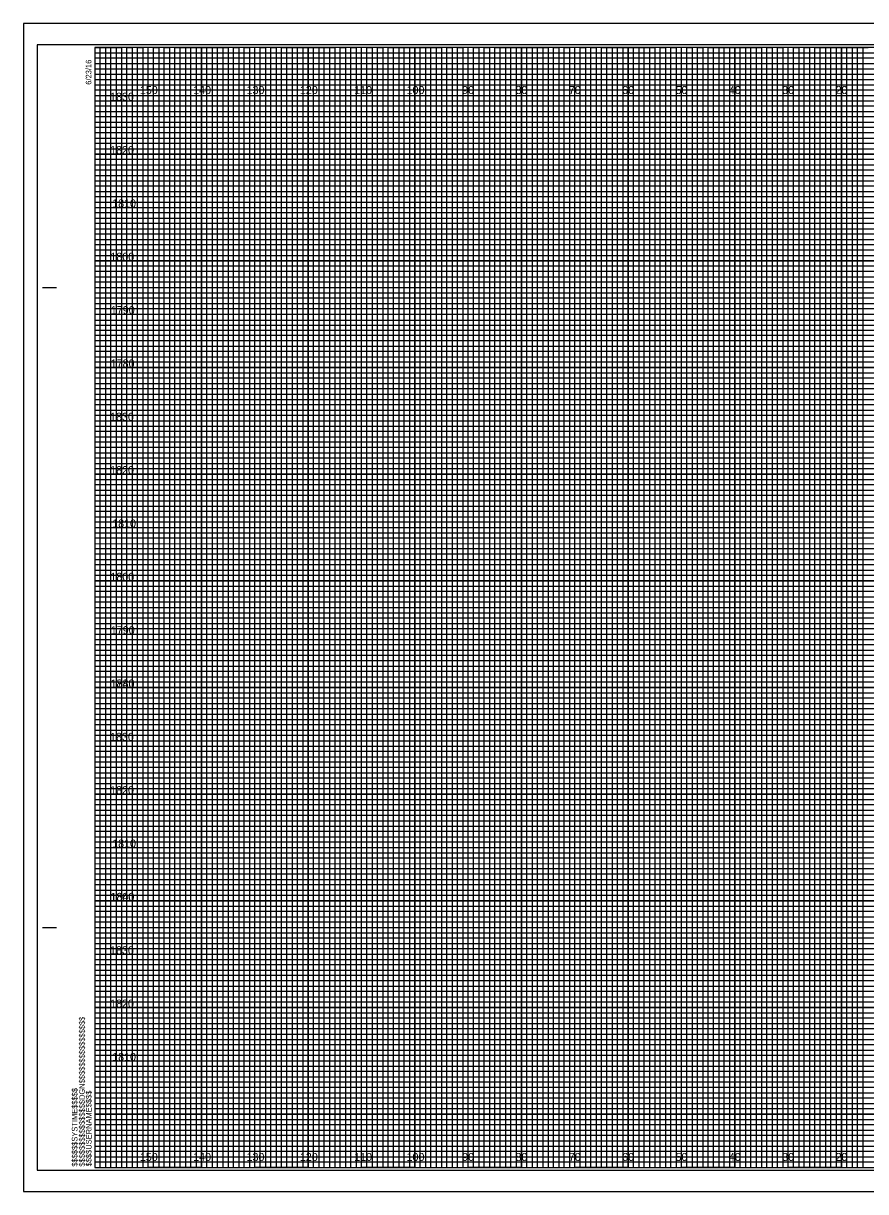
# Model space of a CAD drawing. Extents: x -13 to 323, y -5 to 874.
# Drawn here: x -13.4 to 144.5, y -4.5 to 214.5 of the extents above; entities that cross this region are included whole.
import ezdxf

# ---------------------------------------------------------------- set-up
doc = ezdxf.new("R2010")
doc.units = 0
for name, color, linetype in [('Prop XS Earthwork Shape', 7, 'Continuous'), ('Raster_Level_0', 7, 'Continuous'), ('Scratch_Level_1', 7, 'Continuous'), ('Scratch_Level_3', 7, 'Continuous'), ('Sheet Cross Section CELL', 7, 'Continuous'), ('Sheet Cross Section Grid Minor 1 CELL', 7, 'Continuous'), ('Sheet Cross Section Grid Minor 2 CELL', 7, 'Continuous'), ('Sheet Cutting Line CELL', 7, 'Continuous'), ('Sheet DOT Grid CELL', 7, 'Continuous'), ('Sheet Plot Border Inside CELL', 7, 'Continuous'), ('Sheet Plot Border Outside CELL', 7, 'Continuous')]:
    doc.layers.add(name, color=color, linetype=linetype)

msp = doc.modelspace()

# ---------------------------------------------------------------- linework, layer by layer
at = {"layer": 'Prop XS Earthwork Shape'}
for points in [[(0, 210), (5, 210), (5, 0), (15, 0), (15, 210), (25, 210), (25, 0), (35, 0), (35, 210), (45, 210), (45, 0), (55, 0), (55, 210), (65, 210), (65, 0), (75, 0), (75, 210), (85, 210), (85, 0), (95, 0), (95, 210), (105, 210), (105, 0), (115, 0), (115, 210), (125, 210), (125, 0), (135, 0), (135, 210), (145, 210)], [(0, 205), (275, 205)], [(0, 185), (320, 185), (320, 195), (0, 195)], [(0, 165), (320, 165), (320, 175), (0, 175)], [(0, 145), (320, 145), (320, 155), (0, 155)], [(0, 125), (320, 125), (320, 135), (0, 135)], [(0, 105), (320, 105), (320, 115), (0, 115)], [(0, 85), (320, 85), (320, 95), (0, 95)], [(0, 65), (320, 65), (320, 75), (0, 75)], [(0, 45), (320, 45), (320, 55), (0, 55)], [(0, 25), (320, 25), (320, 35), (0, 35)], [(0, 5), (320, 5), (320, 15), (0, 15)]]:
    msp.add_lwpolyline(points, dxfattribs=at)
at = {"layer": 'Scratch_Level_1'}
for p, q in [((10, 210), (0, 210)), ((10, 0), (10, 210)), ((30, 210), (20, 210)), ((20, 210), (20, 0)), ((30, 0), (30, 210)), ((50, 210), (40, 210)), ((40, 210), (40, 0)), ((50, 0), (50, 210)), ((70, 210), (60, 210)), ((60, 210), (60, 0)), ((70, 0), (70, 210)), ((90, 210), (80, 210)), ((80, 210), (80, 0)), ((90, 0), (90, 210)), ((110, 210), (100, 210)), ((100, 210), (100, 0)), ((110, 0), (110, 210)), ((130, 210), (120, 210)), ((120, 210), (120, 0)), ((130, 0), (130, 210)), ((150, 210), (140, 210)), ((140, 210), (140, 0)), ((20, 0), (10, 0)), ((40, 0), (30, 0)), ((60, 0), (50, 0)), ((80, 0), (70, 0)), ((100, 0), (90, 0)), ((120, 0), (110, 0)), ((140, 0), (130, 0))]:
    msp.add_line(p, q, dxfattribs=at)
for points in [[(0, 200), (320, 200), (320, 190), (0, 190)], [(0, 180), (320, 180), (320, 170), (0, 170)], [(0, 160), (320, 160), (320, 150), (0, 150)], [(0, 140), (320, 140), (320, 130), (0, 130)], [(0, 120), (320, 120), (320, 110), (0, 110)], [(0, 100), (320, 100), (320, 90), (0, 90)], [(0, 80), (320, 80), (320, 70), (0, 70)], [(0, 60), (320, 60), (320, 50), (0, 50)], [(0, 40), (320, 40), (320, 30), (0, 30)], [(0, 20), (320, 20), (320, 10), (0, 10)]]:
    msp.add_lwpolyline(points, dxfattribs=at)
at = {"layer": 'Sheet Cross Section CELL'}
for p, q in [((-9.8, 165), (-7.3, 165)), ((-9.7, 165), (-7.2, 165)), ((-9.8, 45), (-7.3, 45)), ((-9.7, 45), (-7.2, 45)), ((0, 0), (0, 0)), ((0, 0), (0, 0)), ((0, 0), (0, 0)), ((0, 0), (0, 0)), ((0, 0), (0, 0)), ((0, 0), (0, 0)), ((0, 0), (0, 0))]:
    msp.add_line(p, q, dxfattribs=at)
msp.add_lwpolyline([(320, 210), (0, 210), (0, 0), (320, 0)], close=True, dxfattribs=at)
at = {"layer": 'Sheet Cross Section Grid Minor 1 CELL'}
for p, q in [((0, 209), (260, 209)), ((260, 207.98), (0, 207.98)), ((0, 207.98), (0, 207)), ((0, 207), (260, 207)), ((260, 205.89), (0, 205.89)), ((0, 205.89), (0, 204)), ((0, 204), (320, 204))]:
    msp.add_line(p, q, dxfattribs=at)
for points in [[(0, 203), (270, 203), (320, 203), (320, 202), (0, 202)], [(0, 201), (320, 201), (320, 199), (0, 199)], [(0, 198), (320, 198), (320, 197), (0, 196.98)], [(0, 196), (320, 196), (320, 194), (0, 194)], [(0, 193), (320, 193), (320, 192), (0, 192)], [(0, 191), (320, 191), (320, 189), (0, 189)], [(0, 188), (320, 188), (320, 187), (0, 187)], [(0, 186), (320, 186), (320, 184), (0, 184)], [(0, 183), (320, 183), (320, 182), (0, 182)], [(0, 181), (320, 181), (320, 179), (0, 179)], [(0, 178), (320, 178), (320, 177), (0, 177)], [(0, 176), (320, 176), (320, 173.95), (320, 173), (320, 172), (0, 172)], [(0, 174), (320, 174), (320, 173), (0, 173)], [(0, 171), (320, 171), (320, 169), (0, 169.03)], [(0, 169.03), (320, 169), (320, 168), (0, 168)], [(0, 167), (320, 167), (320, 166), (0, 166)], [(0, 164), (320, 164), (320, 163), (0, 163)], [(0, 162), (320, 162), (320, 161), (0, 161)], [(-0.07, 158.89), (320, 158.89), (320, 157.88), (-0.07, 157.88)], [(0, 157), (320, 157), (320, 156), (0, 156)], [(0, 154), (320, 154), (320, 153), (0, 153)], [(0, 152), (320, 152), (320, 151), (0, 151)], [(0, 149), (320, 149), (320, 148), (0, 148)], [(0, 147), (320, 147), (320, 146), (0, 146)], [(0, 144), (320, 144), (320, 143), (0, 143)], [(0, 142), (320, 142), (320, 141), (0, 141)], [(0, 139), (320, 139), (319.99, 137.98), (0, 138)], [(0, 137), (320, 137), (320, 136), (0, 136)], [(0, 134), (320, 134), (320, 133), (0, 133)], [(0, 132), (320, 132), (320, 131), (0, 131)], [(0, 129), (320, 129), (320, 128), (0, 128)], [(0, 127), (320, 127), (320, 126), (0, 126)], [(0, 124), (320, 124), (320, 123), (0, 123)], [(0, 122), (320, 122), (320, 121), (0, 121)], [(0, 119), (320, 119), (320, 118), (0, 118)], [(0, 116.99), (320.07, 116.91), (320, 116), (0, 116)], [(0, 114), (320, 114), (320, 113), (0, 113)], [(0, 112), (320, 112), (320, 111), (0, 111)], [(0, 109), (320, 109), (320, 108), (0, 108)], [(0, 107), (320, 107), (320, 106), (0, 106)], [(0, 104), (320, 104), (320, 103), (0, 103)], [(0, 102), (320, 102), (320, 101), (0, 101)], [(0, 99), (320, 99), (320, 98), (0, 98)], [(0, 97), (320, 97), (320, 96), (0, 96)], [(0, 94), (320, 94), (320, 93), (0, 93)], [(0, 92), (320, 92), (320, 91), (0, 91)], [(0, 89), (320, 89), (320, 88), (0, 88)], [(0, 87), (320, 87), (320, 86), (0, 86)], [(0, 84), (320, 84), (320, 83), (0, 83)], [(0, 82), (320, 82), (320, 81), (0, 81)], [(0, 79), (320, 79), (319.99, 77.98), (0, 78)], [(0, 77), (320, 77), (320, 76), (0, 76)], [(0, 74), (320, 74), (320, 73), (0, 73)], [(0, 72), (320, 72), (320, 71), (0, 71)], [(0, 69), (320, 69), (320, 68), (0, 68)], [(0, 67), (320, 67), (320, 66), (0, 66)], [(0, 64), (320, 64), (320, 63), (0, 63)], [(0, 62), (320, 62), (320, 61), (0, 61)], [(0, 59), (320, 59), (320, 58), (0, 58)], [(0, 56.99), (320.07, 56.91), (320, 56), (0, 56)], [(0, 54), (320, 54), (320, 53), (0, 53)], [(0, 52), (320, 52), (320, 51), (0, 51)], [(0, 49), (320, 49), (320, 48), (0, 48)], [(0, 47), (320, 47), (320, 46), (0, 46)], [(0, 44), (320, 44), (320, 43), (0, 43)], [(0, 42), (320, 42), (320, 41), (0, 41)], [(0, 39), (320, 39), (320, 38), (0, 38)], [(0, 37), (320, 37), (320, 36), (0, 36)], [(0, 34), (320, 34), (320, 33), (0, 33)], [(0, 32), (320, 32), (320, 31), (0, 31)], [(0, 29), (320, 29), (320, 28), (0, 28)], [(0, 27), (320, 27), (320, 26), (0, 26)], [(0, 24), (320, 24), (320, 23), (0, 23)], [(0, 22), (320, 22), (320, 21), (0, 21)], [(0, 19), (320, 19), (320, 18), (0, 18)], [(0, 17), (320, 17), (320, 16), (0, 16)], [(0, 14), (320, 14), (320, 13), (0, 13)], [(0, 12), (320, 12), (320, 11), (0, 11)], [(0, 9), (320, 9), (320, 8), (0, 8)], [(0, 7), (320, 7), (320, 6), (0, 6)], [(0, 4), (320, 4), (320, 3), (0, 3)], [(0, 2), (320, 2), (320, 1), (0, 1)]]:
    msp.add_lwpolyline(points, dxfattribs=at)
at = {"layer": 'Sheet Cross Section Grid Minor 2 CELL'}
for points in [[(0, 0), (1, 0), (1, 210), (2, 210), (2, 0)], [(2, 0), (3, 0), (3, 210), (4, 210), (4, 0)], [(5, 0), (6, 0), (6, 210), (7, 210), (7, 0)], [(7, 0), (8, 0), (8, 210), (9, 210), (9, 0)], [(10, 0), (11, 0), (11, 210), (12, 210), (12, 0)], [(12, 0), (13, 0), (13, 210), (14, 210), (14, 0)], [(15, 0), (16, 0), (16, 210), (17, 210), (17, 0)], [(17, 0), (18, 0), (18, 210), (19, 210), (19, 0)], [(20, 0), (21, 0), (21, 210), (22, 210), (22, 0)], [(22, 0), (23, 0), (23, 210), (24, 210), (24, 0)], [(25, 0), (26, 0), (26, 210), (27, 210), (27, 0)], [(27, 0), (28, 0), (28, 210), (29, 210), (29, 0)], [(30, 0), (31, 0), (31, 210), (32, 210), (32, 0)], [(32, 0), (33, 0), (33, 210), (34, 210), (34, 0)], [(35, 0), (36, 0), (36, 210), (37, 210), (37, 0)], [(37, 0), (38, 0), (38, 210), (39, 210), (39, 0)], [(40, 0), (41, 0), (41, 210), (42, 210), (42, 0)], [(42, 0), (43, 0), (43, 210), (44, 210), (44, 0)], [(45, 0), (46, 0), (46, 210), (47, 210), (47, 0)], [(47, 0), (48, 0), (48, 210), (49, 210), (49, 0)], [(50, 0), (51, 0), (51, 210), (52, 210), (52, 0)], [(52, 0), (53, 0), (53, 210), (54, 210), (54, 0)], [(55, 0), (56, 0), (56, 210), (57, 210), (57, 0)], [(57, 0), (58, 0), (58, 210), (59, 210), (59, 0)], [(60, 0), (61, 0), (61, 210), (62, 210), (62, 0)], [(62, 0), (63, 0), (63, 210), (64, 210), (64, 0)], [(65, 0), (66, 0), (66, 210), (67, 210), (67, 0)], [(67, 0), (68, 0), (68, 210), (69, 210), (69, 0)], [(70, 0), (71, 0), (71, 210), (72, 210), (72, 0)], [(72, 0), (73, 0), (73, 210), (74, 210), (74, 0)], [(75, 0), (76, 0), (76, 210), (77, 210), (77, 0)], [(77, 0), (78, 0), (78, 210), (79, 210), (79, 0)], [(80, 0), (81, 0), (81, 210), (82, 210), (82, 0)], [(82, 0), (83, 0), (83, 210), (84, 210), (84, 0)], [(85, 0), (86, 0), (86, 210), (87, 210), (87, 0)], [(87, 0), (88, 0), (88, 210), (89, 210), (89, 0)], [(90, 0), (91, 0), (91, 210), (92, 210), (92, 0)], [(92, 0), (93, 0), (93, 210), (94, 210), (94, 0)], [(95, 0), (96, 0), (96, 210), (97, 210), (97, 0)], [(97, 0), (98, 0), (98, 210), (99, 210), (99, 0)], [(100, 0), (101, 0), (101, 210), (102, 210), (102, 0)], [(102, 0), (103, 0), (103, 210), (104, 210), (104, 0)], [(105, 0), (106, 0), (106, 210), (107, 210), (107, 0)], [(107, 0), (108, 0), (108, 210), (109, 210), (109, 0)], [(110, 0), (111, 0), (111, 210), (112, 210), (112, 0)], [(112, 0), (113, 0), (113, 210), (114, 210), (114, 0)], [(115, 0), (116, 0), (116, 210), (117, 210), (117, 0)], [(117, 0), (118, 0), (118, 210), (119, 210), (119, 0)], [(120, 0), (121, 0), (121, 210), (122, 210), (122, 0)], [(122, 0), (123, 0), (123, 210), (124, 210), (124, 0)], [(125, 0), (126, 0), (126, 210), (127, 210), (127, 0)], [(127, 0), (128, 0), (128, 210), (129, 210), (129, 0)], [(130, 0), (131, 0), (131, 210), (132, 210), (132, 0)], [(132, 0), (133, 0), (133, 210), (134, 210), (134, 0)], [(135, 0), (136, 0), (136, 210), (137, 210), (137, 0)], [(137, 0), (138, 0), (138, 210), (139, 210), (139, 0)], [(140, 0), (141, 0), (141, 210), (142, 210), (142, 0)], [(142, 0), (143, 0), (143, 210), (144, 210), (144, 0)]]:
    msp.add_lwpolyline(points, dxfattribs=at)
at = {"layer": 'Sheet Cutting Line CELL'}
for p, q in [((323.3, 214.5), (-13.4, 214.5)), ((-13.4, 214.5), (-13.4, -4.5)), ((-13.4, -4.5), (323.3, -4.5))]:
    msp.add_line(p, q, dxfattribs=at)
at = {"layer": 'Sheet DOT Grid CELL'}
for p, q in [((10, 0), (10, 210)), ((20, 0), (20, 210)), ((30, 0), (30, 210)), ((40, 0), (40, 210)), ((50, 0), (50, 210)), ((60, 0), (60, 210)), ((70, 0), (70, 210)), ((80, 0), (80, 210)), ((90, 0), (90, 210)), ((100, 0), (100, 210)), ((110, 0), (110, 210)), ((120, 0), (120, 210)), ((130, 0), (130, 210)), ((140, 0), (140, 210)), ((0, 200), (320, 200)), ((0, 190), (320, 190)), ((0, 180), (320, 180)), ((0, 170), (320, 170)), ((0, 160), (320, 160)), ((0, 150), (320, 150)), ((0, 140), (320, 140)), ((0, 130), (320, 130)), ((0, 120), (320, 120)), ((0, 110), (320, 110)), ((0, 100), (320, 100)), ((0, 90), (320, 90)), ((0, 80), (320, 80)), ((0, 70), (320, 70)), ((0, 60), (320, 60)), ((0, 50), (320, 50)), ((0, 40), (320, 40)), ((0, 30), (320, 30)), ((0, 20), (320, 20)), ((0, 10), (320, 10))]:
    msp.add_line(p, q, dxfattribs=at)
at = {"layer": 'Sheet Plot Border Inside CELL'}
msp.add_lwpolyline([(-10.8, -0.5), (322.4, -0.5), (322.4, 210.5), (-10.8, 210.5)], close=True, dxfattribs=at)
at = {"layer": 'Sheet Plot Border Outside CELL'}
msp.add_lwpolyline([(-13.4, -4.5), (323.3, -4.5), (323.3, 214.5), (-13.4, 214.5)], close=True, dxfattribs=at)

# ---------------------------------------------------------------- texts
at = {"layer": 'Raster_Level_0'}
for s, p in [('150', (8.44, 201.25)), ('140', (18.44, 201.25)), ('130', (28.44, 201.25)), ('120', (38.44, 201.25)), ('110', (48.62, 201.25)), ('100', (58.44, 201.25)), ('90', (68.86, 201.25)), ('80', (78.86, 201.25)), ('70', (88.86, 201.25)), ('60', (98.86, 201.25)), ('50', (108.86, 201.25)), ('40', (118.86, 201.25)), ('30', (128.86, 201.25)), ('20', (138.86, 201.25)), ('150', (8.44, 1.25)), ('140', (18.44, 1.25)), ('130', (28.44, 1.25)), ('120', (38.44, 1.25)), ('110', (48.62, 1.25)), ('100', (58.44, 1.25)), ('90', (68.86, 1.25)), ('80', (78.86, 1.25)), ('70', (88.86, 1.25)), ('60', (98.86, 1.25)), ('50', (108.86, 1.25)), ('40', (118.86, 1.25)), ('30', (128.86, 1.25)), ('20', (138.86, 1.25))]:
    msp.add_text(s, height=1.5, dxfattribs=at).set_placement(p)
at = {"layer": 'Scratch_Level_3'}
for s, p in [('1830', (2.86, 200)), ('1820', (2.87, 190)), ('1810', (3.25, 180)), ('1800', (2.92, 170)), ('1790', (3, 160)), ('1780', (2.98, 150)), ('1830', (2.86, 140)), ('1820', (2.87, 130)), ('1810', (3.25, 120)), ('1800', (2.92, 110)), ('1790', (3, 100)), ('1840', (2.95, 90)), ('1780', (2.98, 90)), ('1830', (2.86, 80)), ('1820', (2.87, 70)), ('1810', (3.25, 60)), ('1800', (2.92, 50)), ('1840', (2.95, 50)), ('1830', (2.86, 40)), ('1820', (2.87, 30)), ('1810', (3.25, 20))]:
    msp.add_text(s, height=1.5, dxfattribs=at).set_placement(p)
at = {"layer": 'Sheet Cross Section CELL'}
for s, p in [('6/23/16', (-0.65, 203)), ('$$$$$$$$$$$$$$$$DGN$$$$$$$$$$$$$$$$', (-1.88, 0.18)), ('$$$$$$SYSTIME$$$$$', (-3.26, 0.18)), ('$$$$USERNAME$$$$', (-0.62, 0.23))]:
    msp.add_text(s, height=1.05, rotation=90, dxfattribs=at).set_placement(p)

doc.saveas('drawing.dxf')
